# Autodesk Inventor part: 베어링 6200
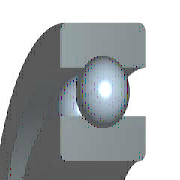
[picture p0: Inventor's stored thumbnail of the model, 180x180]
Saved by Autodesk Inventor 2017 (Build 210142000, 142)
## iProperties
Created: 2012-02
Part Number: 베어링 6200
Material: 강철, 연강
Description: 깊은 그루브 볼 베어링
Document SubType Name: Modeling
Standard: KS B 2023
Designer: mduedu
Standards Organization: KS
Language: ko-KR
Size Designation: 6200 - 10 x 30 x 9
Categories: <MemberInstance><Categories><Category DisplayName="샤프트 부품" InternalName="7f7aeb1f-a693-4053-b835-cee3144e0d98" Mnemonic="SHFT"><Category DisplayName="베어링" Inter
Density: 1 g/cm^3
Appearance: 노란색
IsCustomPart: 1
Author: mduedu
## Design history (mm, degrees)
sketch "스케치" dims "d0" = 5.2 (= -0.26 x WD + 0.26 x BD)
  geometry: L1 (1.9, 10)-(7.1, 10); L2 (4.5, 10)-(4.5, 7.4); L3 (4.5, 10)-(4.5, 12.6); L4 (2.568, 8.26)-(0, 8.26); L5 (0, 5)-(9, 5); L6 (2.568, 11.74)-(0, 11.74); L7 (0, 15)-(9, 15); L8 (9, 5)-(9, 8.26); L9 (6.432, 8.26)-(9, 8.26); L10 (6.432, 11.74)-(9, 11.74); L11 (9, 15)-(9, 11.74); L12 (-1.4, 0)-(8.4, 0) reference; L13 (0, -0.3)-(0, 5.3) reference
  constraints: 22 end point, 4 point on line, 2 collinear, 2 perpendicular, 2 symmetric about line, 1 midpoint, 1 parallel, 14 other
  dimensions: "d9" = 10 diameter of L5 L12 (= WD); "d11" = 30 diameter of L7 L12 (= BD); "d12" = 9 distance between parallel lines of L8 L13 (= KB); "d13" = 16.52 diameter of L9 L12 (= 0.326 x BD + 0.674 x WD)
revolve "본체" stored, may be unused: angle "d6" = 90 deg
revolve "볼" stored, may be unused: angle "d7" = 90 deg
pattern_circular "IDS_ARRAYBALL[SIMPL:T]" dims angle "d3" = 360 deg
body "Solid1"
fillet "모깎기1" dims "d1" = 0.6 (= KRS)
other parameters: "WD" = 10 [user parameter; used in 5 equation terms], "BD" = 30 [user parameter; used in 5 equation terms], "KB" = 9 [user parameter; used in 1 equation term], "KRS" = 0.6 [user parameter; used in 1 equation term], "d4" = 0, "d5" = 0, "d8" = 0, "d14" = 0, "d15" = 0, "BBA" = 0 [user parameter], "BC0" = 2360000 [user parameter], "BC" = 5070000 [user parameter], "BR" = 15 (= 0.5 x BD) [user parameter], "WR" = 5 (= 0.5 x WD) [user parameter]
